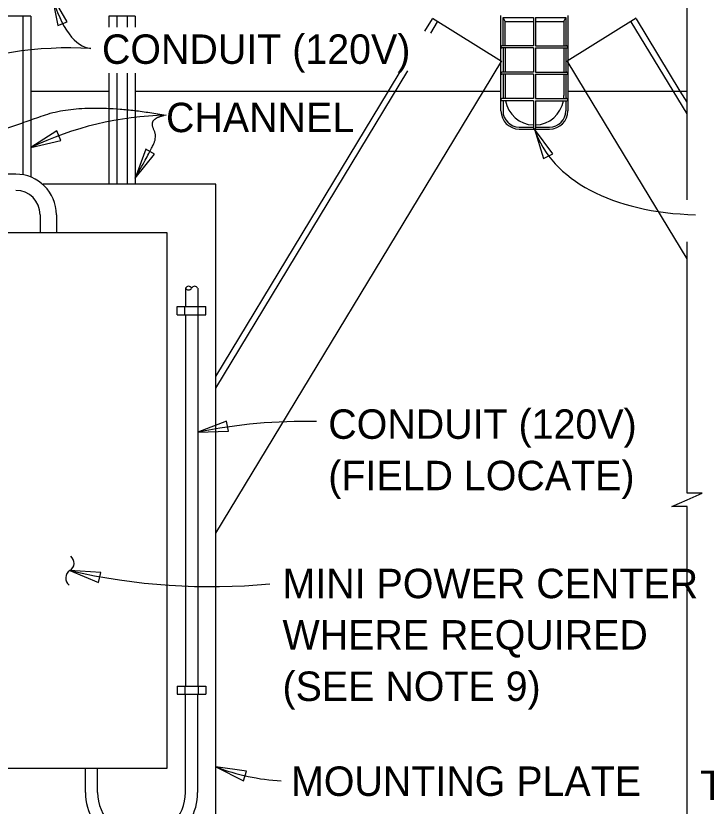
# Model space of a CAD drawing. Extents: x -1660015.2 to -1659984.9, y 2580594.2 to 2580616.7.
# Drawn here: x -1660010.005 to -1660006.46, y 2580598.812 to 2580602.872 of the extents above; entities that cross this region are included whole.
import ezdxf

# ---------------------------------------------------------------- set-up
doc = ezdxf.new("R2010")
doc.units = 0
for name, color, linetype in [('Default', 7, 'Continuous'), ('Miscellaneous', 7, 'Continuous'), ('PlotBorder_dp', 7, 'Continuous'), ('SheetLines_dp', 7, 'Continuous'), ('SteelGirder', 7, 'Continuous')]:
    doc.layers.add(name, color=color, linetype=linetype)

msp = doc.modelspace()

# ---------------------------------------------------------------- linework, layer by layer
at = {"layer": 'Default'}
for p, q in [((-1660009.9277, 2580602.8708), (-1660010.0631, 2580602.8708)), ((-1660009.9693, 2580602.8708), (-1660009.9693, 2580602.0558)), ((-1660009.9277, 2580602.8708), (-1660009.9277, 2580602.044)), ((-1660009.3919, 2580602.8708), (-1660009.5273, 2580602.8708)), ((-1660009.5273, 2580602.8708), (-1660009.5273, 2580602.8144)), ((-1660009.4857, 2580602.8708), (-1660009.4857, 2580602.8144)), ((-1660009.4335, 2580602.8708), (-1660009.4335, 2580602.8144)), ((-1660009.3919, 2580602.8708), (-1660009.3919, 2580602.8144)), ((-1660007.9042, 2580602.794), (-1660007.8659, 2580602.8574)), ((-1660007.8645, 2580602.8596), (-1660007.5106, 2580602.6395)), ((-1660007.5135, 2580602.3841), (-1660007.5135, 2580602.8737)), ((-1660007.5031, 2580602.7174), (-1660007.5031, 2580602.8633)), ((-1660007.5031, 2580602.8633), (-1660007.3469, 2580602.8633)), ((-1660007.4927, 2580602.8425), (-1660007.5031, 2580602.8633)), ((-1660007.3469, 2580602.8633), (-1660007.3469, 2580602.7174)), ((-1660007.3365, 2580602.8633), (-1660007.1802, 2580602.8633)), ((-1660007.3365, 2580602.8633), (-1660007.3365, 2580602.7174)), ((-1660007.1906, 2580602.8425), (-1660007.1802, 2580602.8633)), ((-1660007.1802, 2580602.8633), (-1660007.1802, 2580602.7174)), ((-1660006.8191, 2580602.8596), (-1660007.173, 2580602.6395)), ((-1660007.1698, 2580602.8737), (-1660007.1698, 2580602.3841)), ((-1660006.5926, 2580602.4853), (-1660006.8177, 2580602.8574)), ((-1660007.8741, 2580602.7836), (-1660007.8392, 2580602.8413)), ((-1660007.4927, 2580602.8425), (-1660007.3469, 2580602.8425)), ((-1660007.3365, 2580602.8425), (-1660007.1906, 2580602.8425)), ((-1660006.558, 2580602.3679), (-1660006.8444, 2580602.8413)), ((-1660007.3469, 2580602.7174), (-1660007.5083, 2580602.7174)), ((-1660007.3469, 2580602.707), (-1660007.5083, 2580602.707)), ((-1660007.5031, 2580602.707), (-1660007.5031, 2580602.582)), ((-1660007.3469, 2580602.707), (-1660007.3469, 2580602.582)), ((-1660007.3365, 2580602.7174), (-1660007.175, 2580602.7174)), ((-1660007.3365, 2580602.707), (-1660007.175, 2580602.707)), ((-1660007.3365, 2580602.707), (-1660007.3365, 2580602.582)), ((-1660007.1802, 2580602.707), (-1660007.1802, 2580602.582)), ((-1660007.6038, 2580602.4853), (-1660007.5092, 2580602.6417)), ((-1660007.0797, 2580602.4853), (-1660007.1743, 2580602.6417)), ((-1660009.5273, 2580602.5776), (-1660009.5273, 2580602.0077)), ((-1660009.4857, 2580602.5776), (-1660009.4857, 2580602.0077)), ((-1660009.4335, 2580602.5776), (-1660009.4335, 2580602.0077)), ((-1660009.3919, 2580602.5776), (-1660009.3919, 2580602.0077)), ((-1660008.9775, 2580600.9595), (-1660007.9917, 2580602.5892)), ((-1660008.091, 2580602.4853), (-1660008.0253, 2580602.5938)), ((-1660007.3469, 2580602.582), (-1660007.5083, 2580602.582)), ((-1660007.3469, 2580602.5716), (-1660007.5083, 2580602.5716)), ((-1660007.5031, 2580602.5716), (-1660007.5031, 2580602.4466)), ((-1660007.3469, 2580602.5716), (-1660007.3469, 2580602.4466)), ((-1660007.3365, 2580602.582), (-1660007.175, 2580602.582)), ((-1660007.3365, 2580602.5716), (-1660007.175, 2580602.5716)), ((-1660007.3365, 2580602.5716), (-1660007.3365, 2580602.4466)), ((-1660007.1802, 2580602.5716), (-1660007.1802, 2580602.4466)), ((-1660007.3469, 2580602.4466), (-1660007.5083, 2580602.4466)), ((-1660007.3365, 2580602.4466), (-1660007.175, 2580602.4466)), ((-1660007.3469, 2580602.4362), (-1660007.5083, 2580602.4362)), ((-1660007.5031, 2580602.4362), (-1660007.5031, 2580602.3841)), ((-1660007.3469, 2580602.4362), (-1660007.3469, 2580602.2956)), ((-1660007.3365, 2580602.4362), (-1660007.175, 2580602.4362)), ((-1660007.3365, 2580602.4362), (-1660007.3365, 2580602.2956)), ((-1660007.1802, 2580602.4362), (-1660007.1802, 2580602.3841)), ((-1660007.4198, 2580602.3008), (-1660007.3469, 2580602.3008)), ((-1660007.4198, 2580602.2904), (-1660007.2635, 2580602.2904)), ((-1660007.3365, 2580602.3008), (-1660007.2635, 2580602.3008)), ((-1660010.0052, 2580602.0589), (-1660010.514, 2580602.0591)), ((-1660009.8803, 2580601.8505), (-1660009.8803, 2580601.7577)), ((-1660009.7969, 2580601.8506), (-1660009.7969, 2580601.7577)), ((-1660009.1338, 2580601.4733), (-1660009.1338, 2580601.3782)), ((-1660009.0712, 2580601.4733), (-1660009.0712, 2580601.3782)), ((-1660009.1338, 2580601.3365), (-1660009.1338, 2580599.4289)), ((-1660009.0712, 2580601.3365), (-1660009.0712, 2580599.4289)), ((-1660009.1338, 2580598.8827), (-1660009.1338, 2580599.3872)), ((-1660009.0712, 2580598.8827), (-1660009.0712, 2580599.3872)), ((-1660009.6476, 2580598.8827), (-1660009.6476, 2580599.0077)), ((-1660009.5851, 2580598.8827), (-1660009.5851, 2580599.0077))]:
    msp.add_line(p, q, dxfattribs=at)
msp.add_lwpolyline([(-1660009.2275, 2580601.7577), (-1660010.2275, 2580601.7577), (-1660010.2275, 2580599.0077), (-1660009.2275, 2580599.0077)], close=True, dxfattribs=at)
for centre, radius, start, end in [((-1660007.5083, 2580602.7122), 0.0052, 89.9999, 270), ((-1660007.175, 2580602.7122), 0.0052, 270, 90.0001), ((-1660007.5083, 2580602.5768), 0.0052, 89.9999, 270), ((-1660007.175, 2580602.5768), 0.0052, 270, 90.0001), ((-1660007.5083, 2580602.4414), 0.0052, 89.9999, 270), ((-1660007.175, 2580602.4414), 0.0052, 270, 90.0001), ((-1660007.4198, 2580602.3841), 0.0937, 180, 270), ((-1660007.4198, 2580602.3841), 0.0833, 180, 270), ((-1660007.2635, 2580602.3841), 0.0833, 270, 360), ((-1660007.2635, 2580602.3841), 0.0937, 270, 360), ((-1660007.3417, 2580602.2956), 0.0052, 179.9665, 0), ((-1660010.0052, 2580601.8506), 0.2083, 0, 89.9792), ((-1660010.0053, 2580601.8505), 0.125, 0, 89.9792), ((-1660009.1182, 2580601.4646), 0.0179, 29.0027, 150.9974), ((-1660009.1182, 2580601.482), 0.0179, 209.003, 330.9971), ((-1660009.0869, 2580601.4646), 0.0179, 29.0028, 150.9973), ((-1660009.3595, 2580598.8827), 0.2882, 179.9955, 0.0001), ((-1660009.3595, 2580598.8827), 0.2257, 180, 0)]:
    msp.add_arc(centre, radius, start, end, dxfattribs=at)
at = {"layer": 'Miscellaneous'}
for p, q in [((-1660007.4927, 2580602.7174), (-1660007.4927, 2580602.8425)), ((-1660007.1906, 2580602.8425), (-1660007.1906, 2580602.7174)), ((-1660007.4927, 2580602.707), (-1660007.4927, 2580602.582)), ((-1660007.1906, 2580602.707), (-1660007.1906, 2580602.582)), ((-1660007.4927, 2580602.5716), (-1660007.4927, 2580602.4622)), ((-1660007.1906, 2580602.5716), (-1660007.1906, 2580602.4622))]:
    msp.add_line(p, q, dxfattribs=at)
for start, end in [(180, 185.9203), (354.0797, 0), (189.9053, 268.0265), (271.9735, 350.0947)]:
    msp.add_arc((-1660007.3417, 2580602.4622), 0.151, start, end, dxfattribs=at)
at = {"layer": 'SheetLines_dp'}
for points in [[(-1660006.558, 2580601.9272), (-1660006.558, 2580604.252)], [(-1660006.558, 2580596.5919), (-1660006.558, 2580600.3516), (-1660006.6355, 2580600.3516), (-1660006.558, 2580600.3853), (-1660006.4805, 2580600.4191), (-1660006.558, 2580600.4191), (-1660006.558, 2580601.7115)]]:
    msp.add_lwpolyline(points, dxfattribs=at)
for points in [[(-1660009.8205, 2580602.9778), (-1660009.7901, 2580602.8223), (-1660009.7406, 2580602.841)], [(-1660007.3417, 2580602.2903), (-1660007.2944, 2580602.1391), (-1660007.2472, 2580602.1632)], [(-1660009.9277, 2580602.1953), (-1660009.7736, 2580602.2318), (-1660009.7942, 2580602.2805)], [(-1660009.3919, 2580602.0384), (-1660009.2921, 2580602.1614), (-1660009.3382, 2580602.1874)], [(-1660009.0712, 2580600.733), (-1660008.9129, 2580600.7381), (-1660008.9234, 2580600.79)], [(-1660009.7272, 2580600.0226), (-1660009.581, 2580599.9615), (-1660009.5691, 2580600.0131)], [(-1660008.9775, 2580599.0141), (-1660008.8364, 2580598.9421), (-1660008.8206, 2580598.9926)]]:
    msp.add_lwpolyline(points, close=True, dxfattribs=at)
for centre, radius, start, end in [((-1660009.7245, 2580600.7276), 1.9799, 86.9707, 110.5746), ((-1660009.1966, 2580600.6748), 1.6871, 91.2604, 115.6789), ((-1660008.5194, 2580598.0152), 2.7733, 88.7814, 101.4782), ((-1660009.7504, 2580600.0603), 0.0447, 301.142, 52.8692), ((-1660009.7042, 2580599.9837), 0.0447, 121.142, 232.8692), ((-1660009.0011, 2580603.1581), 3.2185, 256.9627, 275.3449), ((-1660008.5868, 2580600.0223), 1.0813, 248.8193, 267.0903)]:
    msp.add_arc(centre, radius, start, end, dxfattribs=at)
for centre, major_axis, ratio, start_param, end_param in [((-1660009.5408, 2580603.775), (0.079, 1.0703), 0.315754, 2.434073, 3.141613), ((-1660006.0404, 2580602.7272), (1.3013, 0.4369), 0.58496, 3.141593, 4.152777)]:
    msp.add_ellipse(centre, major_axis=major_axis, ratio=ratio, start_param=start_param, end_param=end_param, dxfattribs=at)
for points in [[(-1660010.2171, 2580602.2353), (-1660010.0702, 2580602.2883), (-1660009.6473, 2580602.4352), (-1660009.2337, 2580602.3615)], [(-1660009.3919, 2580602.0384), (-1660009.3152, 2580602.1744), (-1660009.2798, 2580602.2529), (-1660009.3098, 2580602.3149), (-1660009.2877, 2580602.3507), (-1660009.2427, 2580602.3613)]]:
    msp.add_open_spline(points, degree=2, dxfattribs=at)
at = {"layer": 'SteelGirder'}
for p, q in [((-1660009.9277, 2580602.4853), (-1660009.5273, 2580602.4853)), ((-1660009.3919, 2580602.4853), (-1660007.5136, 2580602.4853)), ((-1660008.9775, 2580601.0197), (-1660008.091, 2580602.4853)), ((-1660008.9775, 2580600.2145), (-1660007.6038, 2580602.4853)), ((-1660007.1699, 2580602.4853), (-1660006.558, 2580602.4853)), ((-1660006.558, 2580601.6229), (-1660007.0797, 2580602.4853)), ((-1660006.558, 2580602.4282), (-1660006.5926, 2580602.4853)), ((-1660009.1758, 2580601.3782), (-1660009.0292, 2580601.3782)), ((-1660009.1758, 2580601.3365), (-1660009.1758, 2580601.3782)), ((-1660009.1364, 2580601.3365), (-1660009.1364, 2580601.3782)), ((-1660009.0686, 2580601.3365), (-1660009.0686, 2580601.3782)), ((-1660009.0292, 2580601.3365), (-1660009.0292, 2580601.3782)), ((-1660009.1758, 2580601.3365), (-1660009.0292, 2580601.3365)), ((-1660009.1758, 2580599.4289), (-1660009.0292, 2580599.4289)), ((-1660009.1758, 2580599.4289), (-1660009.1758, 2580599.3872)), ((-1660009.1364, 2580599.4289), (-1660009.1364, 2580599.3872)), ((-1660009.0686, 2580599.4289), (-1660009.0686, 2580599.3872)), ((-1660009.0292, 2580599.4289), (-1660009.0292, 2580599.3872)), ((-1660009.1758, 2580599.3872), (-1660009.0292, 2580599.3872))]:
    msp.add_line(p, q, dxfattribs=at)
msp.add_lwpolyline([(-1660009.0999, 2580598.7577), (-1660008.9775, 2580598.7577), (-1660008.9775, 2580602.0077), (-1660009.8656, 2580602.0077)], dxfattribs=at)

# ---------------------------------------------------------------- texts
at = {"layer": 'PlotBorder_dp'}
for s, p in [('CONDUIT (120V)', (-1660009.5628, 2580602.6254)), ('CHANNEL', (-1660009.2337, 2580602.2745)), ('MOUNTING PLATE', (-1660008.5917, 2580598.8647))]:
    msp.add_text(s, height=0.1512, dxfattribs=at).set_placement(p)
at = {"layer": 'SheetLines_dp'}
for s, p in [('CONDUIT (120V)', (-1660008.4005, 2580600.6991)), ('(FIELD LOCATE)', (-1660008.4005, 2580600.4351)), ('MINI POWER CENTER', (-1660008.6354, 2580599.8804)), ('WHERE REQUIRED', (-1660008.6354, 2580599.6164)), ('(SEE NOTE 9)', (-1660008.6354, 2580599.3524)), ('TRANSVERSE', (-1660006.4909, 2580598.8439))]:
    msp.add_text(s, height=0.1512, dxfattribs=at).set_placement(p)

doc.saveas('drawing.dxf')
